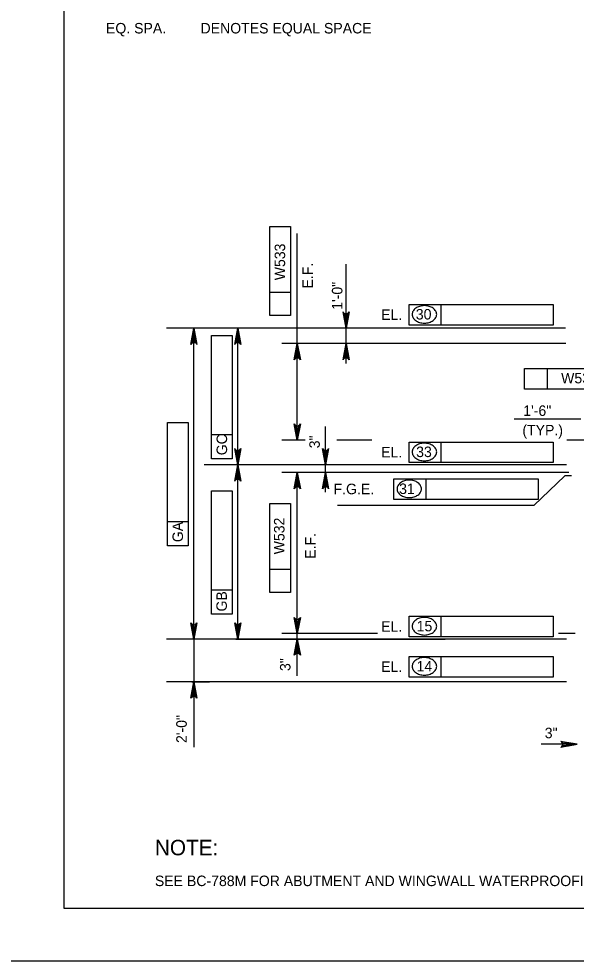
# Model space of a CAD drawing. Extents: x 638255 to 640306, y 296059 to 298435.
# Drawn here: x 639303.6 to 639462.6, y 297247.5 to 297516.7 of the extents above; entities that cross this region are included whole.
import ezdxf

# ---------------------------------------------------------------- set-up
doc = ezdxf.new("R2010")
doc.units = 0
for name, color, linetype in [('2', 7, 'Continuous'), ('4', 7, 'Continuous'), ('Level 3', 7, 'Continuous'), ('Level 4', 7, 'Continuous'), ('PLT-BNDY', 7, 'Continuous')]:
    doc.layers.add(name, color=color, linetype=linetype)

msp = doc.modelspace()

# ---------------------------------------------------------------- linework, layer by layer
at = {"layer": '2'}
for p, q in [((639316.46, 297262.46), (639316.46, 297826.46)), ((640102.46, 297262.46), (639316.46, 297262.46))]:
    msp.add_line(p, q, dxfattribs=at)
at = {"layer": 'Level 3'}
for p, q in [((639463.92, 297402.3), (639444.95, 297402.3)), ((639461.33, 297386.17), (639459.38, 297386.17))]:
    msp.add_line(p, q, dxfattribs=at)
at = {"layer": 'Level 4'}
for p, q in [((639375.16, 297431.92), (639375.16, 297457.4)), ((639375.16, 297457.4), (639381.05, 297457.4)), ((639381.05, 297457.4), (639381.05, 297431.92)), ((639383.04, 297399.25), (639383.04, 297455.39)), ((639396.97, 297418.26), (639396.97, 297446.56)), ((639381.05, 297438.49), (639375.16, 297438.49)), ((639414.95, 297435.09), (639456.08, 297435.09)), ((639414.95, 297429.19), (639414.95, 297435.09)), ((639424.1, 297429.19), (639424.1, 297435.09)), ((639456.08, 297435.09), (639456.08, 297429.19)), ((639381.05, 297431.92), (639375.16, 297431.92)), ((639459.6, 297428.29), (639345.71, 297428.29)), ((639361.05, 297428.29), (639349.1, 297428.29)), ((639378.42, 297428.29), (639361.63, 297428.29)), ((639425.36, 297428.29), (639389.6, 297428.29)), ((639456.08, 297429.19), (639414.95, 297429.19)), ((639353.52, 297342.45), (639353.52, 297425.34)), ((639358.53, 297390.98), (639358.53, 297426.22)), ((639358.53, 297426.22), (639364.42, 297426.22)), ((639364.42, 297426.22), (639364.42, 297390.98)), ((639366.05, 297392.18), (639366.05, 297425.34)), ((639459.71, 297423.93), (639378.61, 297423.93)), ((639447.9, 297416.81), (639473.39, 297416.81)), ((639447.9, 297410.91), (639447.9, 297416.81)), ((639454.48, 297410.91), (639454.48, 297416.81)), ((639473.39, 297410.91), (639447.9, 297410.91)), ((639346.01, 297366.12), (639346.01, 297401.35)), ((639346.01, 297401.35), (639351.9, 297401.35)), ((639351.9, 297401.35), (639351.9, 297366.12)), ((639391.09, 297381.42), (639391.09, 297400.19)), ((639364.42, 297397.82), (639358.53, 297397.82)), ((639385.24, 297396.3), (639378.61, 297396.3)), ((639404.27, 297396.3), (639394.27, 297396.3)), ((639414.95, 297395.78), (639456.08, 297395.78)), ((639414.95, 297389.89), (639414.95, 297395.78)), ((639424.1, 297389.89), (639424.1, 297395.78)), ((639456.08, 297395.78), (639456.08, 297389.89)), ((639475.97, 297396.3), (639459.98, 297396.3)), ((639364.42, 297390.98), (639358.53, 297390.98)), ((639456.08, 297389.89), (639414.95, 297389.89)), ((639459.88, 297389.24), (639356.45, 297389.24)), ((639431.76, 297389.24), (639361.63, 297389.24)), ((639425.36, 297389.24), (639361.63, 297389.24)), ((639460.49, 297387.09), (639378.61, 297387.09)), ((639366.05, 297342.45), (639366.05, 297386.29)), ((639383.04, 297339.5), (639383.04, 297384.14)), ((639410.61, 297385.23), (639451.74, 297385.23)), ((639410.61, 297379.34), (639410.61, 297385.23)), ((639419.77, 297379.34), (639419.77, 297385.23)), ((639459.38, 297386.17), (639450.56, 297377.67)), ((639451.74, 297385.23), (639451.74, 297379.34)), ((639358.53, 297346.59), (639358.53, 297381.83)), ((639358.53, 297381.83), (639364.42, 297381.83)), ((639364.42, 297381.83), (639364.42, 297346.59)), ((639451.74, 297379.34), (639410.61, 297379.34)), ((639375.16, 297352.75), (639375.16, 297378.23)), ((639375.16, 297378.23), (639381.05, 297378.23)), ((639381.05, 297378.23), (639381.05, 297352.75)), ((639450.56, 297377.67), (639394.53, 297377.67)), ((639351.9, 297372.95), (639346.01, 297372.95)), ((639351.9, 297366.12), (639346.01, 297366.12)), ((639381.05, 297359.33), (639375.16, 297359.33)), ((639364.42, 297353.43), (639358.53, 297353.43)), ((639381.05, 297352.75), (639375.16, 297352.75)), ((639364.42, 297346.59), (639358.53, 297346.59)), ((639414.95, 297345.99), (639456.08, 297345.99)), ((639414.95, 297340.09), (639414.95, 297345.99)), ((639424.1, 297340.09), (639424.1, 297345.99)), ((639456.08, 297345.99), (639456.08, 297340.09)), ((639405.88, 297341.04), (639378.61, 297341.04)), ((639462.35, 297341.04), (639457.59, 297341.04)), ((639459.88, 297339.5), (639345.71, 297339.5)), ((639361.05, 297339.5), (639349.1, 297339.5)), ((639353.52, 297339.5), (639353.52, 297327.23)), ((639431.76, 297339.5), (639361.63, 297339.5)), ((639365.45, 297339.5), (639425.19, 297339.5)), ((639456.08, 297340.09), (639414.95, 297340.09)), ((639383.04, 297328.96), (639383.04, 297336.56)), ((639414.95, 297334.52), (639456.08, 297334.52)), ((639414.95, 297328.63), (639414.95, 297334.52)), ((639424.1, 297328.63), (639424.1, 297334.52)), ((639456.08, 297334.52), (639456.08, 297328.63)), ((639456.08, 297328.63), (639414.95, 297328.63)), ((639386.49, 297327.23), (639345.71, 297327.23)), ((639352.93, 297327.23), (639357.95, 297327.23)), ((639459.88, 297327.23), (639386.49, 297327.23)), ((639353.52, 297324.28), (639353.52, 297308.64)), ((639456.97, 297309.42), (639452.6, 297309.42)), ((639459.92, 297309.42), (639456.97, 297309.42))]:
    msp.add_line(p, q, dxfattribs=at)
for points in [[(639396.97, 297428.29), (639396.1, 297432.94), (639396.35, 297432.58), (639396.66, 297432.4), (639396.97, 297432.34), (639397.28, 297432.4), (639397.59, 297432.58), (639397.84, 297432.94), (639396.97, 297428.29), (639397.59, 297432.58), (639397.28, 297432.4), (639396.97, 297428.29), (639396.97, 297432.34), (639396.66, 297432.4), (639396.97, 297428.29), (639396.35, 297432.58)], [(639353.52, 297428.29), (639354.4, 297423.64), (639354.15, 297423.99), (639353.84, 297424.18), (639353.52, 297424.23), (639353.21, 297424.18), (639352.9, 297423.99), (639352.65, 297423.64), (639353.52, 297428.29), (639352.9, 297423.99), (639353.21, 297424.18), (639353.52, 297428.29), (639353.52, 297424.23), (639353.84, 297424.18), (639353.52, 297428.29), (639354.15, 297423.99)], [(639366.05, 297428.29), (639366.92, 297423.64), (639366.67, 297423.99), (639366.36, 297424.18), (639366.05, 297424.23), (639365.74, 297424.18), (639365.43, 297423.99), (639365.18, 297423.64), (639366.05, 297428.29), (639365.43, 297423.99), (639365.74, 297424.18), (639366.05, 297428.29), (639366.05, 297424.23), (639366.36, 297424.18), (639366.05, 297428.29), (639366.67, 297423.99)], [(639383.04, 297423.93), (639383.91, 297419.28), (639383.66, 297419.63), (639383.35, 297419.82), (639383.04, 297419.87), (639382.72, 297419.82), (639382.41, 297419.63), (639382.16, 297419.28), (639383.04, 297423.93), (639382.41, 297419.63), (639382.72, 297419.82), (639383.04, 297423.93), (639383.04, 297419.87), (639383.35, 297419.82), (639383.04, 297423.93), (639383.66, 297419.63)], [(639396.97, 297423.93), (639397.84, 297419.28), (639397.59, 297419.63), (639397.28, 297419.82), (639396.97, 297419.87), (639396.66, 297419.82), (639396.35, 297419.63), (639396.1, 297419.28), (639396.97, 297423.93), (639396.35, 297419.63), (639396.66, 297419.82), (639396.97, 297423.93), (639396.97, 297419.87), (639397.28, 297419.82), (639396.97, 297423.93), (639397.59, 297419.63)], [(639383.04, 297396.3), (639382.16, 297400.95), (639382.41, 297400.59), (639382.72, 297400.41), (639383.04, 297400.35), (639383.35, 297400.41), (639383.66, 297400.59), (639383.91, 297400.95), (639383.04, 297396.3), (639383.66, 297400.59), (639383.35, 297400.41), (639383.04, 297396.3), (639383.04, 297400.35), (639382.72, 297400.41), (639383.04, 297396.3), (639382.41, 297400.59)], [(639366.05, 297389.24), (639365.18, 297393.89), (639365.43, 297393.53), (639365.74, 297393.35), (639366.05, 297393.29), (639366.36, 297393.35), (639366.67, 297393.53), (639366.92, 297393.89), (639366.05, 297389.24), (639366.67, 297393.53), (639366.36, 297393.35), (639366.05, 297389.24), (639366.05, 297393.29), (639365.74, 297393.35), (639366.05, 297389.24), (639365.43, 297393.53)], [(639391.09, 297389.24), (639390.22, 297393.89), (639390.47, 297393.53), (639390.78, 297393.35), (639391.09, 297393.29), (639391.4, 297393.35), (639391.72, 297393.53), (639391.96, 297393.89), (639391.09, 297389.24), (639391.72, 297393.53), (639391.4, 297393.35), (639391.09, 297389.24), (639391.09, 297393.29), (639390.78, 297393.35), (639391.09, 297389.24), (639390.47, 297393.53)], [(639366.05, 297389.24), (639366.92, 297384.59), (639366.67, 297384.94), (639366.36, 297385.13), (639366.05, 297385.18), (639365.74, 297385.13), (639365.43, 297384.94), (639365.18, 297384.59), (639366.05, 297389.24), (639365.43, 297384.94), (639365.74, 297385.13), (639366.05, 297389.24), (639366.05, 297385.18), (639366.36, 297385.13), (639366.05, 297389.24), (639366.67, 297384.94)], [(639383.04, 297387.09), (639383.91, 297382.44), (639383.66, 297382.79), (639383.35, 297382.98), (639383.04, 297383.03), (639382.72, 297382.98), (639382.41, 297382.79), (639382.16, 297382.44), (639383.04, 297387.09), (639382.41, 297382.79), (639382.72, 297382.98), (639383.04, 297387.09), (639383.04, 297383.03), (639383.35, 297382.98), (639383.04, 297387.09), (639383.66, 297382.79)], [(639391.09, 297387.09), (639391.96, 297382.44), (639391.72, 297382.79), (639391.4, 297382.98), (639391.09, 297383.03), (639390.78, 297382.98), (639390.47, 297382.79), (639390.22, 297382.44), (639391.09, 297387.09), (639390.47, 297382.79), (639390.78, 297382.98), (639391.09, 297387.09), (639391.09, 297383.03), (639391.4, 297382.98), (639391.09, 297387.09), (639391.72, 297382.79)], [(639353.52, 297339.5), (639352.65, 297344.16), (639352.9, 297343.8), (639353.21, 297343.61), (639353.52, 297343.56), (639353.84, 297343.61), (639354.15, 297343.8), (639354.4, 297344.16), (639353.52, 297339.5), (639354.15, 297343.8), (639353.84, 297343.61), (639353.52, 297339.5), (639353.52, 297343.56), (639353.21, 297343.61), (639353.52, 297339.5), (639352.9, 297343.8)], [(639366.05, 297339.5), (639365.18, 297344.16), (639365.43, 297343.8), (639365.74, 297343.61), (639366.05, 297343.56), (639366.36, 297343.61), (639366.67, 297343.8), (639366.92, 297344.16), (639366.05, 297339.5), (639366.67, 297343.8), (639366.36, 297343.61), (639366.05, 297339.5), (639366.05, 297343.56), (639365.74, 297343.61), (639366.05, 297339.5), (639365.43, 297343.8)], [(639383.04, 297341.04), (639382.16, 297345.69), (639382.41, 297345.33), (639382.72, 297345.15), (639383.04, 297345.1), (639383.35, 297345.15), (639383.66, 297345.33), (639383.91, 297345.69), (639383.04, 297341.04), (639383.66, 297345.33), (639383.35, 297345.15), (639383.04, 297341.04), (639383.04, 297345.1), (639382.72, 297345.15), (639383.04, 297341.04), (639382.41, 297345.33)], [(639383.04, 297339.5), (639383.91, 297334.85), (639383.66, 297335.21), (639383.35, 297335.4), (639383.04, 297335.45), (639382.72, 297335.4), (639382.41, 297335.21), (639382.16, 297334.85), (639383.04, 297339.5), (639382.41, 297335.21), (639382.72, 297335.4), (639383.04, 297339.5), (639383.04, 297335.45), (639383.35, 297335.4), (639383.04, 297339.5), (639383.66, 297335.21)], [(639353.52, 297327.23), (639354.4, 297322.57), (639354.15, 297322.93), (639353.84, 297323.12), (639353.52, 297323.17), (639353.21, 297323.12), (639352.9, 297322.93), (639352.65, 297322.57), (639353.52, 297327.23), (639352.9, 297322.93), (639353.21, 297323.12), (639353.52, 297327.23), (639353.52, 297323.17), (639353.84, 297323.12), (639353.52, 297327.23), (639354.15, 297322.93)], [(639462.87, 297309.42), (639458.21, 297308.54), (639458.57, 297308.79), (639458.76, 297309.1), (639458.81, 297309.42), (639458.76, 297309.73), (639458.57, 297310.04), (639458.21, 297310.29), (639462.87, 297309.42), (639458.57, 297310.04), (639458.76, 297309.73), (639462.87, 297309.42), (639458.81, 297309.42), (639458.76, 297309.1), (639462.87, 297309.42), (639458.57, 297308.79)]]:
    msp.add_lwpolyline(points, dxfattribs=at)
for points in [[(639396.48, 297431.23), (639397.46, 297431.23), (639396.97, 297428.29)], [(639353.03, 297425.34), (639354.02, 297425.34), (639353.52, 297428.29)], [(639365.56, 297425.34), (639366.54, 297425.34), (639366.05, 297428.29)], [(639382.54, 297420.98), (639383.53, 297420.98), (639383.04, 297423.93)], [(639396.48, 297420.98), (639397.46, 297420.98), (639396.97, 297423.93)], [(639382.54, 297399.25), (639383.53, 297399.25), (639383.04, 297396.3)], [(639365.56, 297392.18), (639366.54, 297392.18), (639366.05, 297389.24)], [(639390.6, 297392.18), (639391.58, 297392.18), (639391.09, 297389.24)], [(639365.56, 297386.29), (639366.54, 297386.29), (639366.05, 297389.24)], [(639382.54, 297384.14), (639383.53, 297384.14), (639383.04, 297387.09)], [(639390.6, 297384.14), (639391.58, 297384.14), (639391.09, 297387.09)], [(639382.54, 297343.99), (639383.53, 297343.99), (639383.04, 297341.04)], [(639353.03, 297342.45), (639354.02, 297342.45), (639353.52, 297339.5)], [(639365.56, 297342.45), (639366.54, 297342.45), (639366.05, 297339.5)], [(639382.54, 297336.56), (639383.53, 297336.56), (639383.04, 297339.5)], [(639353.03, 297324.28), (639354.02, 297324.28), (639353.52, 297327.23)], [(639459.92, 297309.91), (639459.92, 297308.92), (639462.87, 297309.42)]]:
    msp.add_lwpolyline(points, close=True, dxfattribs=at)
for centre, radius, start, end in [((639417.64, 297432.25), 1.82, 149.9767, 180), ((639418.45, 297431.78), 2.75, 125.6316, 149.9767), ((639418.97, 297431.05), 3.65, 106.5358, 125.6316), ((639419.32, 297429.89), 4.86, 90, 106.5358), ((639419.32, 297429.89), 4.86, 73.4642, 90), ((639419.66, 297431.05), 3.65, 54.3684, 73.4642), ((639420.19, 297431.78), 2.75, 30.0233, 54.3684), ((639420.99, 297432.25), 1.82, 0, 30.0233), ((639417.64, 297432.25), 1.82, 180, 210.0233), ((639418.45, 297432.71), 2.75, 210.0233, 234.3684), ((639418.97, 297433.45), 3.65, 234.3684, 253.4642), ((639419.32, 297434.6), 4.86, 253.4642, 270), ((639419.32, 297434.6), 4.86, 270, 286.5358), ((639419.66, 297433.45), 3.65, 286.5358, 305.6316), ((639420.19, 297432.71), 2.75, 305.6316, 329.9767), ((639420.99, 297432.25), 1.82, 329.9767, 0), ((639418.45, 297392.47), 2.75, 125.6316, 149.9767), ((639418.97, 297391.74), 3.65, 106.5358, 125.6316), ((639419.32, 297390.58), 4.86, 90, 106.5358), ((639419.32, 297390.58), 4.86, 73.4642, 90), ((639419.66, 297391.74), 3.65, 54.3684, 73.4642), ((639420.19, 297392.47), 2.75, 30.0233, 54.3684), ((639417.64, 297392.94), 1.82, 149.9767, 180), ((639417.64, 297392.94), 1.82, 180, 210.0233), ((639418.45, 297393.4), 2.75, 210.0233, 234.3684), ((639420.19, 297393.4), 2.75, 305.6316, 329.9767), ((639420.99, 297392.94), 1.82, 0, 30.0233), ((639420.99, 297392.94), 1.82, 329.9767, 0), ((639418.97, 297394.14), 3.65, 234.3684, 253.4642), ((639419.32, 297395.29), 4.86, 253.4642, 270), ((639419.32, 297395.29), 4.86, 270, 286.5358), ((639419.66, 297394.14), 3.65, 286.5358, 305.6316), ((639414.11, 297381.93), 2.75, 125.6316, 149.9767), ((639414.64, 297381.19), 3.65, 106.5358, 125.6316), ((639414.98, 297380.04), 4.86, 90, 106.5358), ((639414.98, 297380.04), 4.86, 73.4642, 90), ((639415.32, 297381.19), 3.65, 54.3684, 73.4642), ((639415.85, 297381.93), 2.75, 30.0233, 54.3684), ((639413.31, 297382.39), 1.82, 149.9767, 180), ((639413.31, 297382.39), 1.82, 180, 210.0233), ((639414.11, 297382.86), 2.75, 210.0233, 234.3684), ((639415.85, 297382.86), 2.75, 305.6316, 329.9767), ((639416.65, 297382.39), 1.82, 0, 30.0233), ((639416.65, 297382.39), 1.82, 329.9767, 0), ((639414.64, 297383.59), 3.65, 234.3684, 253.4642), ((639414.98, 297384.75), 4.86, 253.4642, 270), ((639414.98, 297384.75), 4.86, 270, 286.5358), ((639415.32, 297383.59), 3.65, 286.5358, 305.6316), ((639417.64, 297343.15), 1.82, 149.9767, 180), ((639418.45, 297342.68), 2.75, 125.6316, 149.9767), ((639418.97, 297341.95), 3.65, 106.5358, 125.6316), ((639419.32, 297340.79), 4.86, 90, 106.5358), ((639419.32, 297340.79), 4.86, 73.4642, 90), ((639419.66, 297341.95), 3.65, 54.3684, 73.4642), ((639420.19, 297342.68), 2.75, 30.0233, 54.3684), ((639420.99, 297343.15), 1.82, 0, 30.0233), ((639417.64, 297343.15), 1.82, 180, 210.0233), ((639418.45, 297343.61), 2.75, 210.0233, 234.3684), ((639418.97, 297344.35), 3.65, 234.3684, 253.4642), ((639419.32, 297345.5), 4.86, 253.4642, 270), ((639419.32, 297345.5), 4.86, 270, 286.5358), ((639419.66, 297344.35), 3.65, 286.5358, 305.6316), ((639420.19, 297343.61), 2.75, 305.6316, 329.9767), ((639420.99, 297343.15), 1.82, 329.9767, 0), ((639418.45, 297331.22), 2.75, 125.6316, 149.9767), ((639418.97, 297330.48), 3.65, 106.5358, 125.6316), ((639419.32, 297329.33), 4.86, 90, 106.5358), ((639419.32, 297329.33), 4.86, 73.4642, 90), ((639419.66, 297330.48), 3.65, 54.3684, 73.4642), ((639420.19, 297331.22), 2.75, 30.0233, 54.3684), ((639417.64, 297331.68), 1.82, 149.9767, 180), ((639417.64, 297331.68), 1.82, 180, 210.0233), ((639418.45, 297332.15), 2.75, 210.0233, 234.3684), ((639420.19, 297332.15), 2.75, 305.6316, 329.9767), ((639420.99, 297331.68), 1.82, 0, 30.0233), ((639420.99, 297331.68), 1.82, 329.9767, 0), ((639418.97, 297332.88), 3.65, 234.3684, 253.4642), ((639419.32, 297334.04), 4.86, 253.4642, 270), ((639419.32, 297334.04), 4.86, 270, 286.5358), ((639419.66, 297332.88), 3.65, 286.5358, 305.6316)]:
    msp.add_arc(centre, radius, start, end, dxfattribs=at)
at = {"layer": 'PLT-BNDY'}
msp.add_lwpolyline([(639276.46, 297841.46), (640117.46, 297841.46), (640117.46, 297247.46), (639276.46, 297247.46)], close=True, dxfattribs=at)

# ---------------------------------------------------------------- texts
at = {"layer": '2'}
msp.add_text('SEE BC-788M FOR ABUTMENT AND WINGWALL WATERPROOFING DETAIL.', height=3.0001, dxfattribs=at).set_placement((639342.4, 297268.9))
at = {"layer": '4'}
msp.add_text('NOTE:', height=4.429, dxfattribs=at).set_placement((639342.4, 297277.7))
at = {"layer": 'Level 3'}
for s, p in [('1\'-6"', (639447.52, 297403.25)), ('(TYP.)', (639447.27, 297397.69))]:
    msp.add_text(s, height=3, dxfattribs=at).set_placement(p)
at = {"layer": 'Level 4'}
for s, height, p in [('EQ. SPA.', 3, (639328.44, 297512.52)), ('DENOTES EQUAL SPACE', 3.0001, (639355.42, 297512.52)), ('EL.', 3, (639406.94, 297430.68)), ('30', 3, (639416.86, 297430.79)), ('W534', 3, (639458.32, 297412.54)), ('EL.', 3, (639406.94, 297391.37)), ('33', 3, (639416.96, 297391.48)), ('F.G.E.', 3, (639393.38, 297380.87)), ('31', 3, (639412.1, 297380.93)), ('EL.', 3, (639406.94, 297341.58)), ('15', 3, (639417.1, 297341.69)), ('EL.', 3, (639406.94, 297330.11)), ('14', 3, (639417.07, 297330.22)), ('3"', 3, (639453.65, 297311.15))]:
    msp.add_text(s, height=height, dxfattribs=at).set_placement(p)
for s, p in [('W533', (639379.57, 297442)), ('E.F.', (639387.48, 297439.65)), ('1\'-0"', (639395.91, 297433.56)), ('GC', (639363, 297392)), ('3"', (639389.46, 297393.99)), ('W532', (639379.38, 297363.7)), ('GA', (639350.42, 297367.17)), ('E.F.', (639388.25, 297362.44)), ('GB', (639362.94, 297347.36)), ('3"', (639381.09, 297330.36)), ('2\'-0"', (639351.49, 297309.79))]:
    msp.add_text(s, height=3, rotation=90, dxfattribs=at).set_placement(p)

doc.saveas('drawing.dxf')
